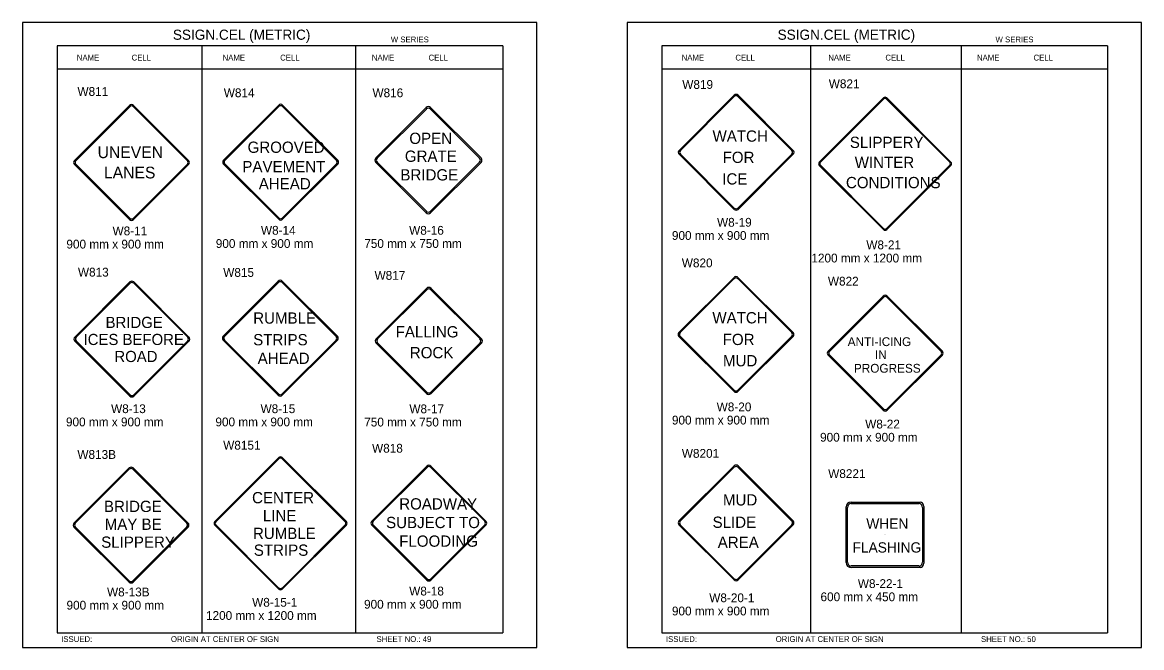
# Model space of a CAD drawing. Extents: x -12 to 6962, y -3756 to 679.
# Drawn here: x 1343.2 to 1724.4, y -235.4 to -22.3 of the extents above; entities that cross this region are included whole.
import ezdxf

# ---------------------------------------------------------------- set-up
doc = ezdxf.new("R2010")
doc.units = 0
for name, color, linetype in [('Level 1', 7, 'Continuous'), ('Level 2', 7, 'Continuous'), ('Level 3', 7, 'Continuous'), ('Level 62', 7, 'Continuous')]:
    doc.layers.add(name, color=color, linetype=linetype)

msp = doc.modelspace()

# ---------------------------------------------------------------- linework, layer by layer
at = {"layer": 'Level 1'}
for p, q in [((1506.83, -30.35), (1355.07, -30.35)), ((1355.07, -30.35), (1355.07, -230.35)), ((1404.28, -30.35), (1404.28, -230.35)), ((1456.7, -30.09), (1456.7, -230.09)), ((1506.83, -30.35), (1506.83, -230.35)), ((1712.82, -30.35), (1561.06, -30.35)), ((1561.06, -30.35), (1561.06, -230.35)), ((1611.65, -30.35), (1611.65, -230.35)), ((1663.03, -30.35), (1663.03, -230.35)), ((1712.82, -30.35), (1712.82, -230.35)), ((1506.83, -38.27), (1355.07, -38.27)), ((1712.82, -38.27), (1561.06, -38.27)), ((1566.88, -65.92), (1585.65, -47.14)), ((1567.32, -65.97), (1585.71, -47.59)), ((1586.94, -47.59), (1605.33, -65.97)), ((1586.99, -47.14), (1605.77, -65.92)), ((1614.64, -69.91), (1636.49, -48.07)), ((1615.03, -69.96), (1636.53, -48.45)), ((1637.59, -48.45), (1659.09, -69.96)), ((1637.63, -48.07), (1659.48, -69.91)), ((1360.94, -69.39), (1379.71, -50.61)), ((1361.38, -69.44), (1379.77, -51.06)), ((1381, -51.06), (1399.39, -69.44)), ((1381.05, -50.61), (1399.83, -69.39)), ((1411.73, -69.28), (1430.5, -50.51)), ((1412.17, -69.34), (1430.56, -50.95)), ((1431.79, -50.95), (1450.18, -69.34)), ((1431.84, -50.51), (1450.62, -69.28)), ((1463.55, -68.52), (1480.74, -51.33)), ((1464.05, -68.58), (1480.8, -51.83)), ((1482.17, -51.83), (1498.92, -68.58)), ((1482.23, -51.33), (1499.42, -68.52)), ((1585.65, -86.04), (1566.88, -67.26)), ((1585.71, -85.59), (1567.32, -67.2)), ((1586.33, -66.62), (1586.33, -66.62)), ((1605.33, -67.2), (1586.94, -85.59)), ((1605.77, -67.26), (1586.99, -86.04)), ((1379.71, -89.51), (1360.94, -70.73)), ((1379.77, -89.06), (1361.38, -70.67)), ((1380.38, -70.06), (1380.38, -70.06)), ((1399.39, -70.67), (1381, -89.06)), ((1399.83, -70.73), (1381.05, -89.51)), ((1430.5, -89.4), (1411.73, -70.63)), ((1430.56, -88.96), (1412.17, -70.57)), ((1431.18, -69.95), (1431.18, -69.95)), ((1450.18, -70.57), (1431.79, -88.96)), ((1450.62, -70.63), (1431.84, -89.4)), ((1480.74, -87.2), (1463.55, -70.01)), ((1480.8, -86.7), (1464.05, -69.95)), ((1481.47, -69.24), (1481.47, -69.24)), ((1498.92, -69.95), (1482.17, -86.7)), ((1499.42, -70.01), (1482.23, -87.2)), ((1636.49, -92.91), (1614.64, -71.06)), ((1636.53, -92.52), (1615.03, -71.02)), ((1636.97, -70.26), (1636.97, -70.26)), ((1659.09, -71.02), (1637.59, -92.52)), ((1659.48, -71.06), (1637.63, -92.91)), ((1411.61, -129.28), (1430.38, -110.5)), ((1431.72, -110.5), (1450.5, -129.28)), ((1566.82, -127.98), (1585.6, -109.2)), ((1567.27, -128.04), (1585.66, -109.65)), ((1586.89, -109.65), (1605.27, -128.04)), ((1586.94, -109.2), (1605.72, -127.98)), ((1361.04, -129.56), (1379.83, -110.78)), ((1361.49, -129.62), (1379.88, -111.22)), ((1381.11, -111.22), (1399.51, -129.62)), ((1381.17, -110.78), (1399.95, -129.56)), ((1412.05, -129.34), (1430.44, -110.95)), ((1431.67, -110.95), (1450.06, -129.34)), ((1463.71, -130.14), (1480.9, -112.95)), ((1464.21, -130.2), (1480.96, -113.45)), ((1482.33, -113.45), (1499.08, -130.2)), ((1482.39, -112.95), (1499.58, -130.14)), ((1617.67, -134.37), (1636.45, -115.59)), ((1618.12, -134.43), (1636.5, -116.04)), ((1637.73, -116.04), (1656.12, -134.43)), ((1637.79, -115.59), (1656.57, -134.37)), ((1585.6, -148.1), (1566.82, -129.32)), ((1585.66, -147.65), (1567.27, -129.27)), ((1586.28, -128.65), (1586.28, -128.65)), ((1605.27, -129.27), (1586.89, -147.65)), ((1605.72, -129.32), (1586.94, -148.1)), ((1379.83, -149.69), (1361.04, -130.9)), ((1379.88, -149.24), (1361.49, -130.85)), ((1380.5, -130.23), (1380.5, -130.23)), ((1380.5, -130.23), (1380.5, -130.23)), ((1399.51, -130.85), (1381.11, -149.24)), ((1399.95, -130.9), (1381.17, -149.69)), ((1430.38, -149.4), (1411.61, -130.62)), ((1430.44, -148.95), (1412.05, -130.57)), ((1431.06, -129.95), (1431.06, -129.95)), ((1450.06, -130.57), (1431.67, -148.95)), ((1450.5, -130.62), (1431.72, -149.4)), ((1480.9, -148.82), (1463.71, -131.63)), ((1480.96, -148.32), (1464.21, -131.57)), ((1481.62, -130.96), (1481.62, -130.96)), ((1499.08, -131.57), (1482.33, -148.32)), ((1499.58, -131.63), (1482.39, -148.82)), ((1636.45, -154.49), (1617.67, -135.71)), ((1636.5, -154.04), (1618.12, -135.65)), ((1637.12, -135.04), (1637.12, -135.04)), ((1656.12, -135.65), (1637.73, -154.04)), ((1656.57, -135.71), (1637.79, -154.49)), ((1408.71, -192.47), (1430.56, -170.62)), ((1409.1, -192.52), (1430.6, -171.01)), ((1431.66, -171.01), (1453.17, -192.52)), ((1431.71, -170.63), (1453.55, -192.47)), ((1360.77, -192.95), (1379.54, -174.17)), ((1361.21, -193), (1379.6, -174.62)), ((1380.83, -174.62), (1399.22, -193)), ((1380.88, -174.17), (1399.66, -192.95)), ((1462.22, -192.29), (1481, -173.51)), ((1462.67, -192.34), (1481.06, -173.96)), ((1482.29, -173.96), (1500.67, -192.34)), ((1482.34, -173.51), (1501.12, -192.29)), ((1566.86, -192.24), (1585.63, -173.47)), ((1567.31, -192.29), (1585.68, -173.92)), ((1586.92, -173.92), (1605.29, -192.29)), ((1586.97, -173.47), (1605.74, -192.24)), ((1625.37, -186.33), (1648.65, -186.33)), ((1625.49, -185.77), (1649, -185.77)), ((1623.79, -206.34), (1623.79, -187.47)), ((1624.25, -206.22), (1624.25, -187.7)), ((1649.77, -187.7), (1649.77, -206.22)), ((1650.22, -187.26), (1650.22, -206.65)), ((1379.54, -213.07), (1360.77, -194.29)), ((1379.6, -212.62), (1361.21, -194.23)), ((1380.22, -193.62), (1380.22, -193.62)), ((1399.22, -194.23), (1380.83, -212.62)), ((1399.66, -194.29), (1380.88, -213.07)), ((1430.56, -215.46), (1408.71, -193.62)), ((1430.6, -215.08), (1409.1, -193.57)), ((1431.13, -193.04), (1431.13, -193.04)), ((1453.17, -193.57), (1431.66, -215.08)), ((1453.55, -193.62), (1431.71, -215.46)), ((1481, -212.41), (1462.22, -193.63)), ((1481.06, -211.96), (1462.67, -193.57)), ((1481.68, -192.96), (1481.68, -192.96)), ((1500.67, -193.57), (1482.29, -211.96)), ((1501.12, -193.63), (1482.34, -212.41)), ((1585.63, -212.35), (1566.86, -193.58)), ((1585.68, -211.9), (1567.31, -193.53)), ((1586.3, -192.91), (1586.3, -192.91)), ((1586.31, -192.91), (1586.31, -192.91)), ((1605.29, -193.53), (1586.92, -211.9)), ((1605.74, -193.58), (1586.97, -212.35)), ((1637.01, -196.96), (1637.01, -196.96)), ((1637.05, -196.95), (1637.05, -196.95)), ((1648.65, -207.58), (1625.36, -207.58)), ((1649, -208.14), (1625.59, -208.14)), ((1355.07, -230.35), (1506.83, -230.35)), ((1561.06, -230.35), (1712.82, -230.35))]:
    msp.add_line(p, q, dxfattribs=at)
for centre, radius, start, end in [((1586.32, -47.81), 0.948, 45, 135), ((1586.32, -48.2), 0.869, 45, 135), ((1637.06, -48.65), 0.813, 45, 135), ((1637.06, -48.98), 0.745, 45, 135), ((1380.38, -51.28), 0.948, 45, 135), ((1380.38, -51.67), 0.869, 45, 135), ((1431.17, -51.18), 0.948, 45, 135), ((1431.17, -51.57), 0.869, 45, 135), ((1481.48, -52.08), 1.06, 45, 135), ((1481.48, -52.52), 0.969, 45, 135), ((1464.3, -69.27), 1.06, 135, 225), ((1464.73, -69.27), 0.969, 135, 225), ((1498.23, -69.27), 0.969, 315, 45), ((1498.67, -69.27), 1.06, 315, 45), ((1567.55, -66.59), 0.948, 135, 225), ((1567.94, -66.59), 0.869, 135, 225), ((1604.71, -66.59), 0.869, 315, 45), ((1605.1, -66.59), 0.948, 315, 45), ((1361.61, -70.06), 0.948, 135, 225), ((1362, -70.06), 0.869, 135, 225), ((1398.77, -70.06), 0.869, 315, 45), ((1399.16, -70.06), 0.948, 315, 45), ((1412.4, -69.95), 0.948, 135, 225), ((1412.79, -69.95), 0.869, 135, 225), ((1449.56, -69.95), 0.869, 315, 45), ((1449.95, -69.95), 0.948, 315, 45), ((1615.22, -70.49), 0.813, 135, 225), ((1615.55, -70.49), 0.745, 135, 225), ((1658.57, -70.49), 0.745, 315, 45), ((1658.9, -70.49), 0.813, 315, 45), ((1481.48, -86.45), 1.06, 225, 315), ((1481.48, -86.02), 0.969, 225, 315), ((1586.32, -85.37), 0.948, 225, 315), ((1586.32, -84.98), 0.869, 225, 315), ((1380.38, -88.83), 0.948, 225, 315), ((1380.38, -88.44), 0.869, 225, 315), ((1431.17, -88.73), 0.948, 225, 315), ((1431.17, -88.34), 0.869, 225, 315), ((1637.06, -92.33), 0.813, 225, 315), ((1637.06, -92), 0.745, 225, 315), ((1380.5, -111.45), 0.949, 45, 135), ((1431.05, -111.17), 0.948, 45, 135), ((1586.27, -109.87), 0.948, 45, 135), ((1586.27, -110.27), 0.869, 45, 135), ((1380.5, -111.84), 0.87, 45, 135), ((1431.05, -111.56), 0.869, 45, 135), ((1481.64, -113.7), 1.06, 45, 135), ((1481.64, -114.13), 0.969, 45, 135), ((1637.12, -116.26), 0.948, 45, 135), ((1637.12, -116.65), 0.869, 45, 135), ((1361.71, -130.23), 0.949, 135, 225), ((1362.11, -130.23), 0.87, 135, 225), ((1398.89, -130.23), 0.87, 315, 45), ((1399.28, -130.23), 0.949, 315, 45), ((1412.28, -129.95), 0.948, 135, 225), ((1412.67, -129.95), 0.869, 135, 225), ((1449.44, -129.95), 0.869, 315, 45), ((1449.83, -129.95), 0.948, 315, 45), ((1567.49, -128.65), 0.948, 135, 225), ((1567.88, -128.65), 0.869, 135, 225), ((1604.66, -128.65), 0.869, 315, 45), ((1605.05, -128.65), 0.948, 315, 45), ((1464.46, -130.89), 1.06, 135, 225), ((1464.89, -130.89), 0.969, 135, 225), ((1498.39, -130.89), 0.969, 315, 45), ((1498.83, -130.89), 1.06, 315, 45), ((1618.34, -135.04), 0.948, 135, 225), ((1618.73, -135.04), 0.869, 135, 225), ((1655.5, -135.04), 0.869, 315, 45), ((1655.9, -135.04), 0.948, 315, 45), ((1481.64, -147.64), 0.969, 225, 315), ((1586.27, -147.43), 0.948, 225, 315), ((1586.27, -147.04), 0.869, 225, 315), ((1380.5, -149.02), 0.949, 225, 315), ((1380.5, -148.63), 0.87, 225, 315), ((1431.05, -148.73), 0.948, 225, 315), ((1431.05, -148.34), 0.869, 225, 315), ((1481.64, -148.07), 1.06, 225, 315), ((1637.12, -153.82), 0.948, 225, 315), ((1637.12, -153.43), 0.869, 225, 315), ((1431.13, -171.2), 0.813, 45, 135), ((1431.13, -171.54), 0.745, 45, 135), ((1380.21, -174.84), 0.948, 45, 135), ((1380.21, -175.23), 0.869, 45, 135), ((1481.67, -174.18), 0.948, 45, 135), ((1481.67, -174.57), 0.869, 45, 135), ((1586.3, -174.14), 0.948, 45, 135), ((1586.3, -174.54), 0.877, 45, 135), ((1625.49, -187.47), 1.7, 90, 180), ((1361.44, -193.62), 0.948, 135, 225), ((1361.83, -193.62), 0.869, 135, 225), ((1398.6, -193.62), 0.869, 315, 45), ((1398.99, -193.62), 0.948, 315, 45), ((1409.29, -193.04), 0.813, 135, 225), ((1409.62, -193.04), 0.745, 135, 225), ((1452.64, -193.04), 0.745, 315, 45), ((1452.97, -193.04), 0.813, 315, 45), ((1462.89, -192.96), 0.948, 135, 225), ((1463.28, -192.96), 0.869, 135, 225), ((1500.06, -192.96), 0.869, 315, 45), ((1500.45, -192.96), 0.948, 315, 45), ((1567.53, -192.91), 0.948, 135, 225), ((1567.93, -192.91), 0.877, 135, 225), ((1604.67, -192.91), 0.877, 315, 45), ((1605.07, -192.91), 0.948, 315, 45), ((1625.59, -206.34), 1.8, 180, 270), ((1380.21, -212.4), 0.948, 225, 315), ((1380.21, -212.01), 0.869, 225, 315), ((1481.67, -211.74), 0.948, 225, 315), ((1481.67, -211.34), 0.869, 225, 315), ((1586.3, -211.68), 0.948, 225, 315), ((1586.3, -211.28), 0.877, 225, 315), ((1431.13, -214.88), 0.813, 225, 315), ((1431.13, -214.55), 0.745, 225, 315)]:
    msp.add_arc(centre, radius, start, end, dxfattribs=at)
for centre, major_axis, start_param, end_param in [((1625.37, -187.7), (0, 1.37), 0, 1.570796), ((1648.65, -187.7), (0, 1.37), 4.712389, 6.283185), ((1649, -187.26), (0, 1.49), 4.712389, 6.283185), ((1625.37, -206.22), (0, -1.37), 4.712389, 6.283185), ((1648.65, -206.22), (0, -1.37), 0, 1.570796), ((1649, -206.65), (0, -1.49), 0, 1.570796)]:
    msp.add_ellipse(centre, major_axis=major_axis, ratio=0.817773, start_param=start_param, end_param=end_param, dxfattribs=at)
at = {"layer": 'Level 62'}
for points in [[(1343.19, -235.4), (1518.46, -235.4), (1518.46, -22.31), (1343.19, -22.31)], [(1549.19, -235.4), (1724.45, -235.4), (1724.45, -22.31), (1549.19, -22.31)]]:
    msp.add_lwpolyline(points, close=True, dxfattribs=at)

# ---------------------------------------------------------------- texts
at = {"layer": 'Level 1'}
for s, height, p in [('OPEN', 3.841, (1475.01, -63.74)), ('WATCH', 3.841, (1578.29, -62.98)), ('UNEVEN', 4, (1368.82, -68.57)), ('GROOVED', 3.841, (1419.91, -66.78)), ('SLIPPERY', 3.841, (1625.05, -65.11)), ('GRATE', 3.841, (1473.48, -69.84)), ('FOR', 3.841, (1581.72, -70.22)), ('WINTER', 3.841, (1626.72, -71.96)), ('LANES', 4, (1370.97, -75.49)), ('PAVEMENT', 3.841, (1418.13, -73.38)), ('BRIDGE', 3.841, (1471.96, -76.19)), ('AHEAD', 3.841, (1423.72, -79.22)), ('ICE', 3.841, (1581.59, -77.58)), ('CONDITIONS', 3.841, (1623.73, -78.82)), ('RUMBLE', 3.841, (1421.82, -125)), ('WATCH', 3.841, (1578.24, -124.91)), ('BRIDGE', 3.8, (1371.54, -126.47)), ('FALLING', 3.841, (1470.34, -129.68)), ('ICES BEFORE', 3.8, (1364.04, -132.27)), ('STRIPS', 3.841, (1421.82, -132.37)), ('FOR', 3.841, (1581.75, -132.28)), ('ANTI-ICING', 3, (1624.33, -132.63)), ('ROCK', 3.841, (1475.17, -136.79)), ('ROAD', 3.8, (1374.53, -138.07)), ('AHEAD', 3.841, (1423.34, -138.71)), ('MUD', 3.841, (1581.84, -139.54)), ('IN', 3, (1633.62, -137.08)), ('PROGRESS', 3, (1626.44, -141.7)), ('CENTER', 3.841, (1421.43, -186.21)), ('BRIDGE', 3.841, (1370.98, -189.18)), ('ROADWAY', 3.841, (1471.56, -188.33)), ('MUD', 3.841, (1581.83, -186.96)), ('LINE', 3.841, (1425.11, -192.36)), ('MAY BE', 3.841, (1371.23, -195.27)), ('SUBJECT TO', 3.841, (1467.09, -194.67)), ('SLIDE', 3.841, (1578.3, -194.58)), ('WHEN', 3.5, (1630.68, -194.89)), ('SLIPPERY', 3.841, (1370.04, -201.37)), ('RUMBLE', 3.841, (1421.73, -198.38)), ('FLOODING', 3.841, (1471.56, -201.02)), ('AREA', 3.841, (1580.06, -201.43)), ('STRIPS', 3.841, (1422.03, -204.1)), ('FLASHING', 3.5, (1625.97, -203))]:
    msp.add_text(s, height=height, dxfattribs=at).set_placement(p)
at = {"layer": 'Level 2'}
for s, p in [('W819', (1567.98, -44.98)), ('W821', (1617.88, -44.73)), ('W811', (1361.96, -47.36)), ('W814', (1411.8, -47.81)), ('W816', (1462.45, -47.81)), ('W820', (1567.82, -105.78)), ('W813', (1362.12, -108.93)), ('W815', (1411.61, -109.04)), ('W817', (1463.16, -110.04)), ('W822', (1617.59, -112.01)), ('W8151', (1411.6, -167.92)), ('W818', (1462.31, -168.95)), ('W8201', (1567.83, -170.7)), ('W813B', (1361.93, -171.07)), ('W8221', (1617.68, -177.6))]:
    msp.add_text(s, height=3, dxfattribs=at).set_placement(p)
at = {"layer": 'Level 3'}
for s, height, p in [('SSIGN.CEL (METRIC)', 3.4642, (1394.45, -28.24)), ('SSIGN.CEL (METRIC)', 3.4642, (1600.45, -28.24)), ('W SERIES', 1.979, (1468.7, -29.12)), ('W SERIES', 1.979, (1674.69, -29.12)), ('NAME', 1.98, (1361.74, -35.31)), ('CELL', 1.98, (1380.41, -35.31)), ('NAME', 1.98, (1411.39, -35.31)), ('CELL', 1.98, (1431.01, -35.31)), ('NAME', 1.98, (1462.24, -35.31)), ('CELL', 1.98, (1481.56, -35.31)), ('NAME', 1.98, (1567.78, -35.31)), ('CELL', 1.98, (1586.07, -35.31)), ('NAME', 1.98, (1617.71, -35.31)), ('CELL', 1.98, (1637.17, -35.31)), ('NAME', 1.98, (1668.36, -35.31)), ('CELL', 1.98, (1687.64, -35.31)), ('W8-19', 3, (1579.82, -91.94)), ('W8-11', 3, (1373.91, -94.88)), ('W8-14', 3, (1424.46, -94.68)), ('W8-16', 3, (1474.94, -94.68)), ('900 mm x 900 mm', 3, (1564.45, -96.44)), ('900 mm x 900 mm', 3, (1358.19, -99.38)), ('900 mm x 900 mm', 3, (1409.08, -99.18)), ('750 mm x 750 mm', 3, (1459.65, -99.18)), ('W8-21', 3, (1630.68, -99.63)), ('1200 mm x 1200 mm', 3, (1611.96, -104.13)), ('W8-13', 3, (1373.41, -155.48)), ('W8-15', 3, (1424.33, -155.48)), ('W8-17', 3, (1475.02, -155.53)), ('W8-20', 3, (1579.7, -154.86)), ('900 mm x 900 mm', 3, (1358.04, -159.98)), ('900 mm x 900 mm', 3, (1408.95, -159.98)), ('750 mm x 750 mm', 3, (1459.64, -160.03)), ('900 mm x 900 mm', 3, (1564.45, -159.36)), ('W8-22', 3, (1630.29, -160.71)), ('900 mm x 900 mm', 3, (1614.92, -165.21)), ('W8-22-1', 3, (1627.79, -215.08)), ('W8-13B', 3, (1372.03, -217.94)), ('W8-18', 3, (1474.96, -217.63)), ('W8-20-1', 3, (1577.17, -219.92)), ('600 mm x 450 mm', 3, (1615.07, -219.58)), ('900 mm x 900 mm', 3, (1358.23, -222.44)), ('W8-15-1', 3, (1421.46, -221.45)), ('900 mm x 900 mm', 3, (1459.58, -222.13)), ('1200 mm x 1200 mm', 3, (1405.74, -225.95)), ('900 mm x 900 mm', 3, (1564.45, -224.42)), ('ISSUED:', 1.98, (1356.41, -233.48)), ('ORIGIN AT CENTER OF SIGN', 1.9795, (1393.8, -233.48)), ('SHEET NO.: 49', 1.9795, (1463.83, -233.48)), ('ISSUED:', 1.98, (1562.41, -233.48)), ('ORIGIN AT CENTER OF SIGN', 1.9795, (1599.79, -233.48)), ('SHEET NO.: 50', 1.9795, (1669.74, -233.48))]:
    msp.add_text(s, height=height, dxfattribs=at).set_placement(p)

doc.saveas('drawing.dxf')
